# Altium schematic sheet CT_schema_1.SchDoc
size 526 x 490 mm
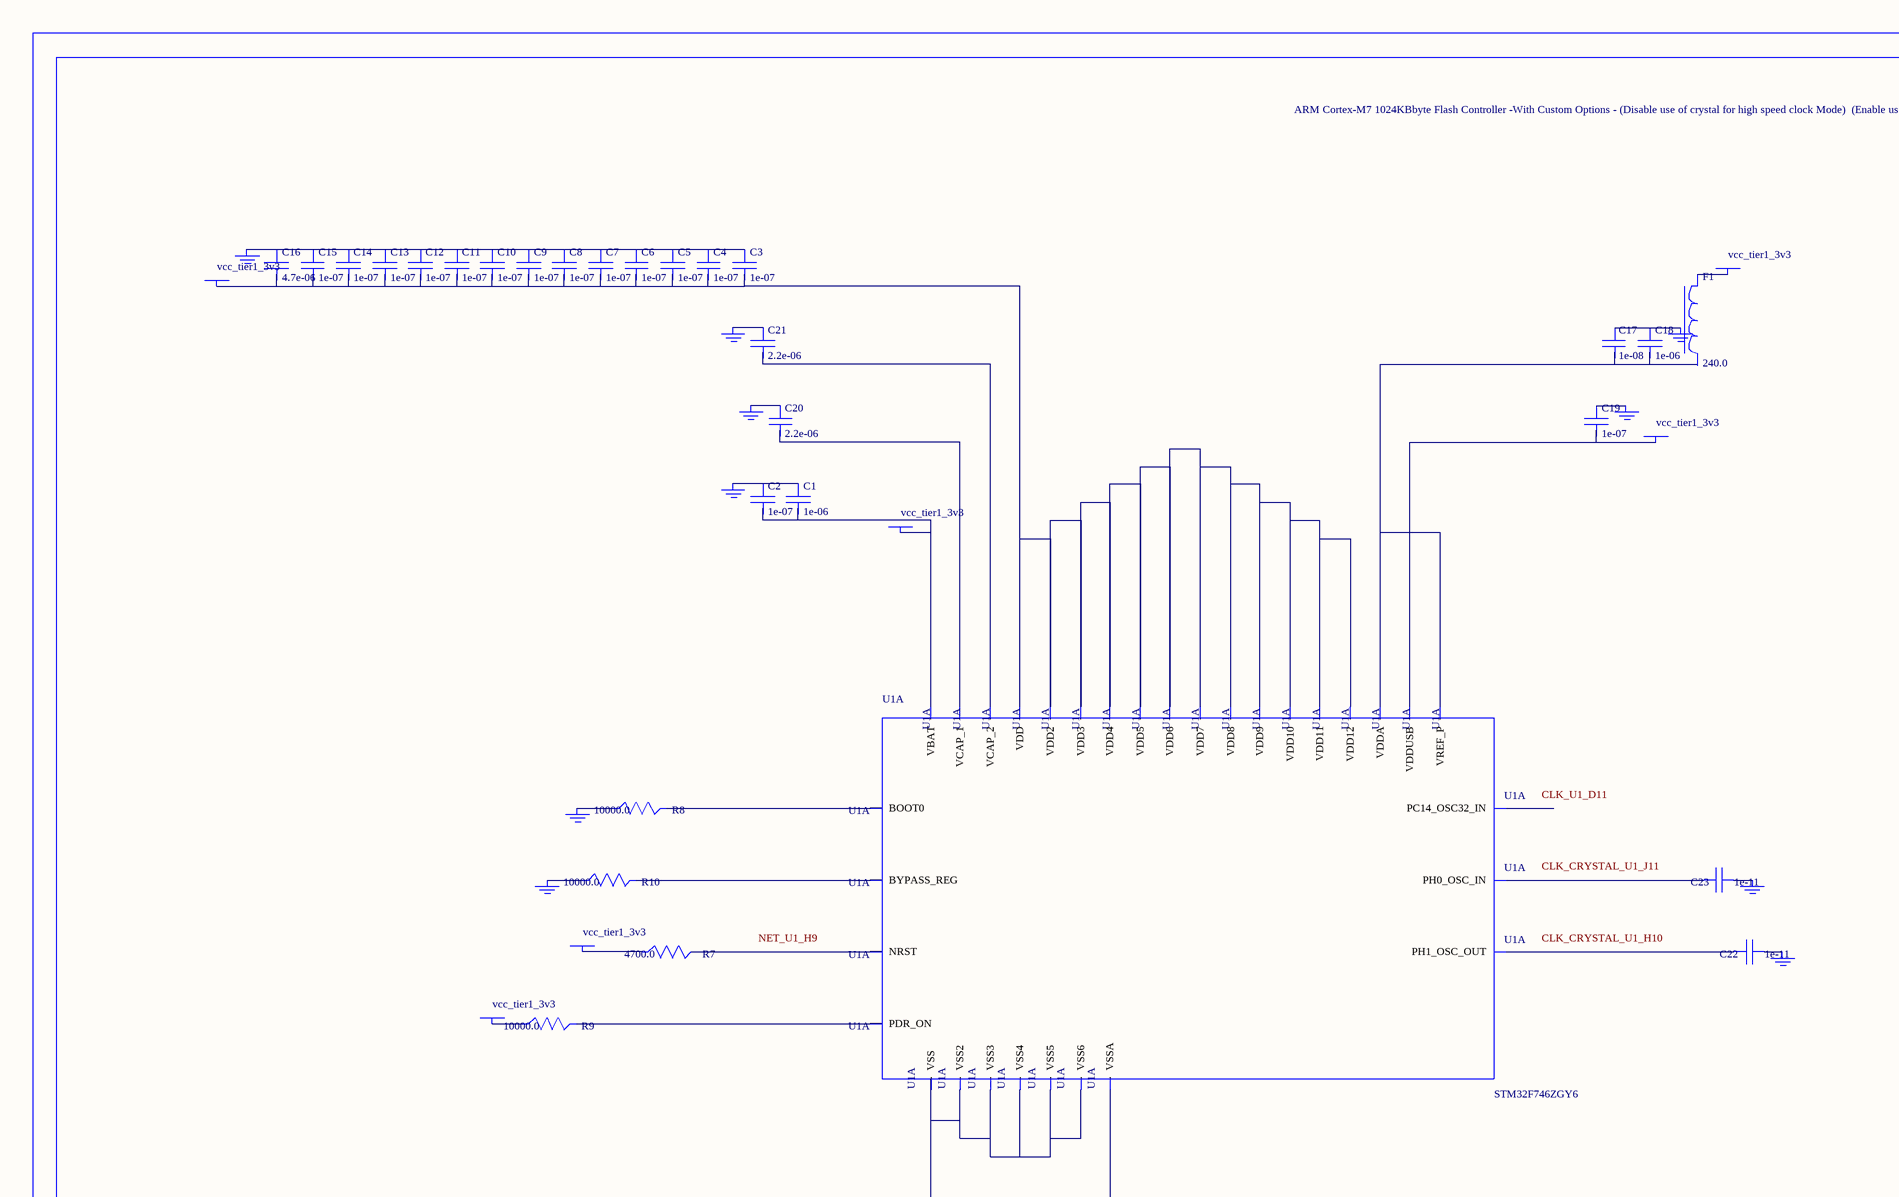
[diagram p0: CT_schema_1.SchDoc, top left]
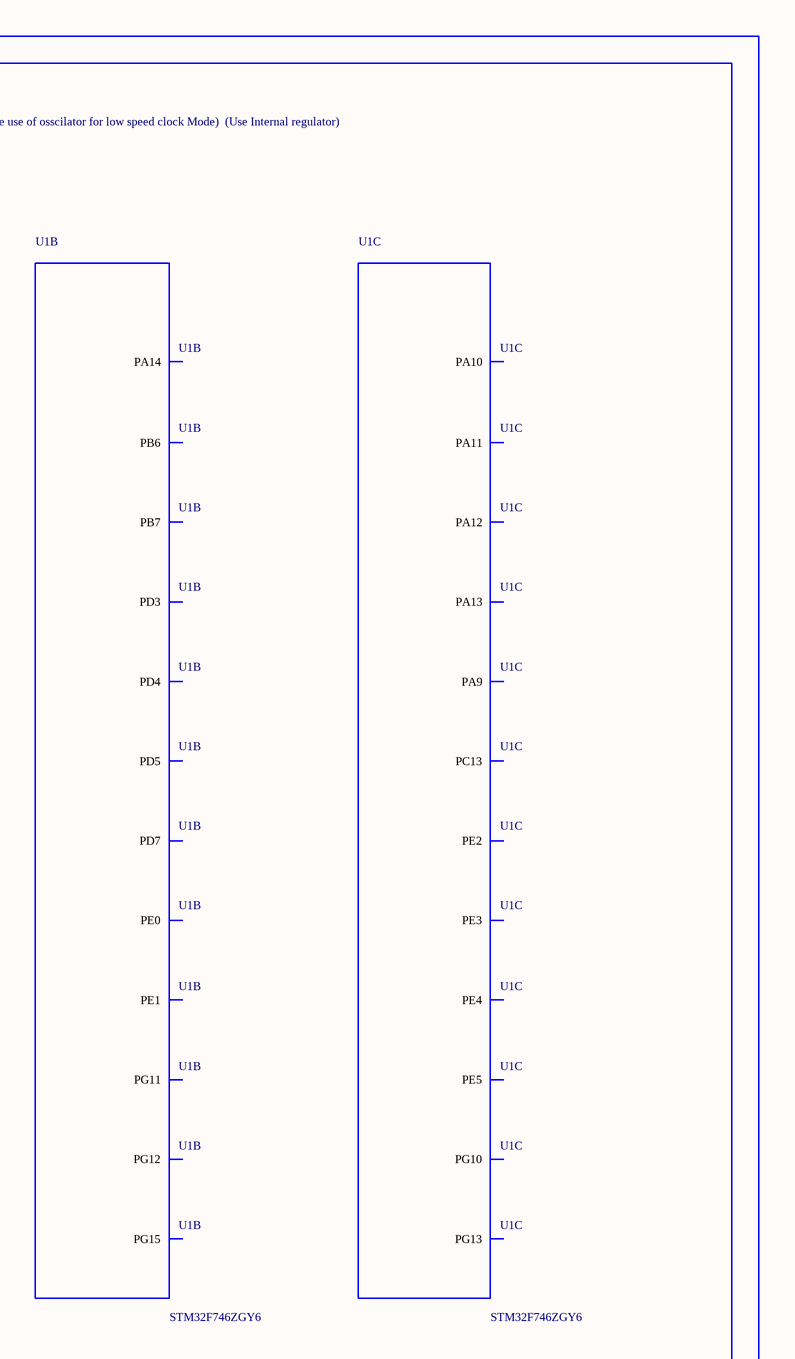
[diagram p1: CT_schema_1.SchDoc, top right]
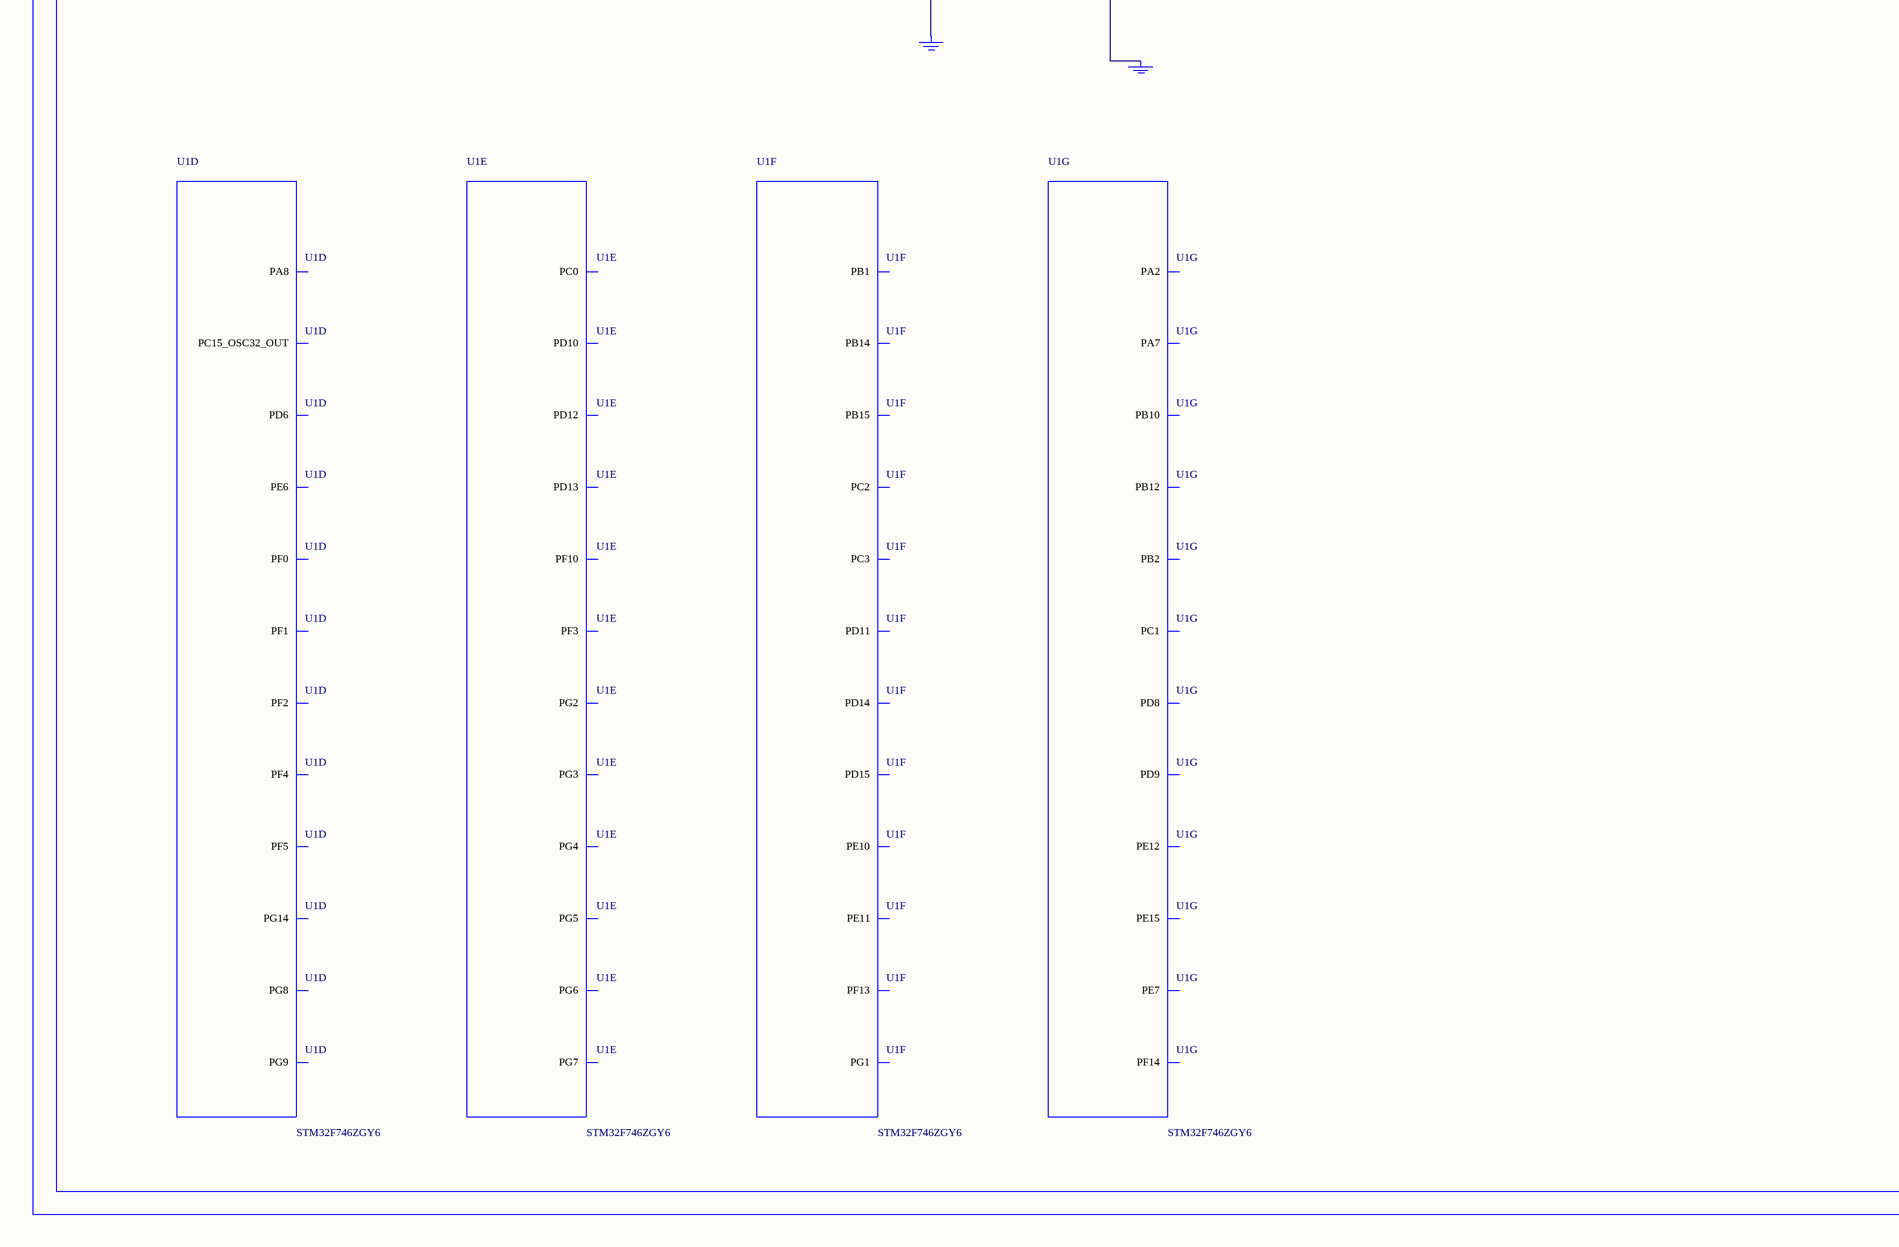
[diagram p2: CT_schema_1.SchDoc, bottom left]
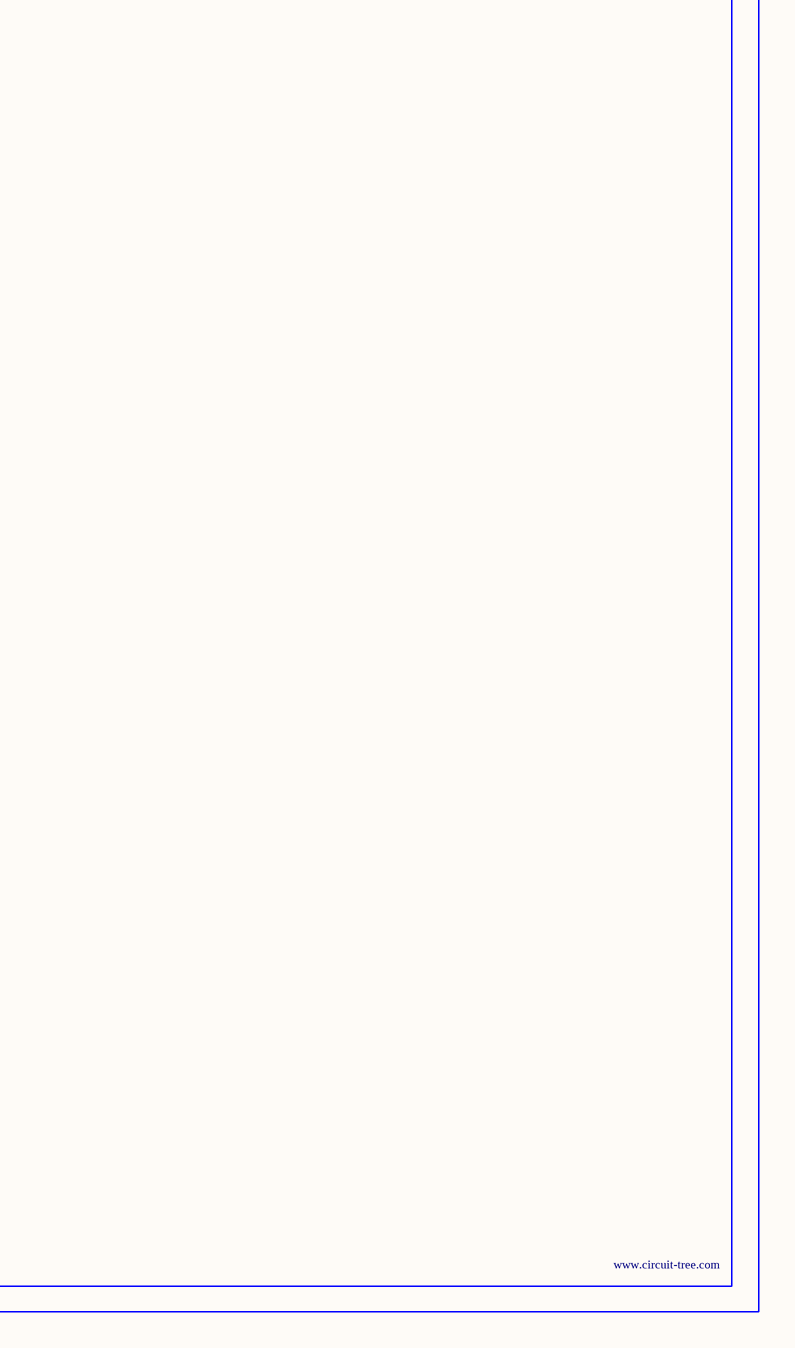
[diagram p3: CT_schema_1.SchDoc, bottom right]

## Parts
BORDER0  (no value)
C1  1e-06  [C0603]
C2  1e-07  [C0603]
C3  1e-07  [C0603]
C4  1e-07  [C0603]
C5  1e-07  [C0603]
C6  1e-07  [C0603]
C7  1e-07  [C0603]
C8  1e-07  [C0603]
C9  1e-07  [C0603]
C10  1e-07  [C0603]
C11  1e-07  [C0603]
C12  1e-07  [C0603]
C13  1e-07  [C0603]
C14  1e-07  [C0603]
C15  1e-07  [C0603]
C16  4.7e-06  [C0603]
C17  1e-08  [C0603]
C18  1e-06  [C0603]
C19  1e-07  [C0603]
C20  2.2e-06  [C0603]
C21  2.2e-06  [C0603]
C22  1e-11  [C0402]
C23  1e-11  [C0402]
F1  240.0  [L0603]
GND_INSTANCE_0_0  (no value)
GND_INSTANCE_0_1  (no value)
GND_INSTANCE_0_2  (no value)
GND_INSTANCE_0_3  (no value)
GND_INSTANCE_0_4  (no value)
GND_INSTANCE_0_5  (no value)
GND_INSTANCE_0_6  (no value)
GND_INSTANCE_0_7  (no value)
GND_INSTANCE_0_8  (no value)
GND_INSTANCE_0_9  (no value)
GND_INSTANCE_0_10  (no value)
GND_INSTANCE_0_11  (no value)
POWER_INSTANCE_0_0  vcc_tier1_3v3
POWER_INSTANCE_0_1  vcc_tier1_3v3
POWER_INSTANCE_0_2  vcc_tier1_3v3
POWER_INSTANCE_0_3  vcc_tier1_3v3
POWER_INSTANCE_0_4  vcc_tier1_3v3
POWER_INSTANCE_0_5  vcc_tier1_3v3
R7  4700.0  [R0603]
R8  10000.0  [R0603]
R9  10000.0  [R0603]
R10  10000.0  [R0603]
U1  STM32F746ZGY6  [WLCSP143]  (parts A,B,C,D,E,F,G of 13)

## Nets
NetC1_1: C1.1 C2.1 GND_INSTANCE_0_0.0(GND)
NetC1_2: C1.2 C2.2 POWER_INSTANCE_0_0.0(PWR) U1.C11(VBAT)
NetC3_1: C3.1 C4.1 C5.1 C6.1 C7.1 C8.1 C9.1 C10.1 C11.1 C12.1 C13.1 C14.1 C15.1 C16.1 GND_INSTANCE_0_2.0(GND)
NetC3_2: C3.2 C4.2 C5.2 C6.2 C7.2 C8.2 C9.2 C10.2 C11.2 C12.2 C13.2 C14.2 C15.2 C16.2 POWER_INSTANCE_0_2.0(PWR) U1.A1(VDD) U1.C1(VDD2) U1.C5(VDD3) U1.D7(VDD4) U1.E6(VDD6) U1.E10(VDD5) U1.G7(VDD7) U1.J5(VDD8) U1.J6(VDD9) U1.J7(VDD10) U1.J8(VDD11) U1.L1(VDD12)
NetC17_1: C17.1 C18.1 GND_INSTANCE_0_1.0(GND)
NetC17_2: C17.2 C18.2 U1.L10(VDDA) U1.L11(VREF_P)
NetC19_1: C19.1 GND_INSTANCE_0_4.0(GND)
NetC19_2: C19.2 POWER_INSTANCE_0_4.0(PWR) U1.G1(VDDUSB)
NetC20_1: C20.1 GND_INSTANCE_0_6.0(GND)
NetC20_2: C20.2 U1.N2(VCAP_1)
NetC21_1: C21.1 GND_INSTANCE_0_7.0(GND)
NetC21_2: C21.2 U1.D1(VCAP_2)
NetC22_1: C22.1 GND_INSTANCE_0_8.0(GND)
NetC22_2: C22.2 U1.H10(PH1_OSC_OUT)
NetC23_1: C23.1 GND_INSTANCE_0_9.0(GND)
NetC23_2: C23.2 U1.J11(PH0_OSC_IN)
NetF1_1: F1.1 POWER_INSTANCE_0_1.0(PWR)
NetGND_INSTANCE_0_3_0: GND_INSTANCE_0_3.0(GND) R8.1
NetGND_INSTANCE_0_5_0: GND_INSTANCE_0_5.0(GND) R10.1
NetGND_INSTANCE_0_10_0: GND_INSTANCE_0_10.0(GND) U1.K10(VSSA)
NetGND_INSTANCE_0_11_0: GND_INSTANCE_0_11.0(GND) U1.D2(VSS) U1.E7(VSS2) U1.F5(VSS3) U1.H2(VSS4) U1.H3(VSS5) U1.H7(VSS6)
NetPOWER_INSTANCE_0_3_0: POWER_INSTANCE_0_3.0(PWR) R9.1
NetPOWER_INSTANCE_0_5_0: POWER_INSTANCE_0_5.0(PWR) R7.1
NetR7_2: R7.2 U1.H9(NRST)
NetR8_2: R8.2 U1.C9(BOOT0)
NetR9_2: R9.2 U1.A11(PDR_ON)
NetR10_2: R10.2 U1.N11(BYPASS_REG)

Not connected (* = marked no-connect by the designer): F1 2; U1 A4(PD5) A5(PD7) A6(PG12) A7(PG15) A8(PB6) A10(PE1) B1(PA14) B4(PD3) B5(PD4) B6(PG11) B8(PB7) B10(PE0) B11(PE4) C6(PG10) C10(PE3) D3(PA13) D4(PA11) D5(PA10) D6(PG13) D8(PE2) D9(PE5) D10(PC13) D11(PC14_OSC32_IN) E1(PA12) E2(PA9) E5(PG9) E8(PE6) E9(PF1) E11(PC15_OSC32_OUT) F1(PA8) F4(PD6) F6(PG14) F8(PF5) F9(PF4) F10(PF2) F11(PF0) G2(PG8) G3(PG3) G4(PG6) G5(PG4) G6(PG5) G9(PF10) G11(PF3) H1(PG7) H4(PD10) H5(PD13) H6(PD12) H8(PC0) J1(PG2) J2(PD14) J3(PB15) J4(PE10) J9(PC3) J10(PC2) K1(PD15) K2(PD11) K3(PB14) K4(PE11) K5(PG1) K6(PF13) K7(PB1) K11(PC1) L2(PD8) L3(PE15) L4(PE12) L5(PE7) L6(PF14) L7(PB2) L8(PA7) L9(PA2) M1(PD9) M2(PB12) M3(PB10)

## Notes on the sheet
- Labels drawn without touching a wire or pin: CLK_CRYSTAL_U1_H10, CLK_CRYSTAL_U1_J11, CLK_U1_D11, NET_U1_H9

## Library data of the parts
BORDER0 = BORDER_PAGE0
C1 C18 = C0603C105K3RACTU
C2-C15 C19 = 06035C104K4Z2A
C16 = GRM188R6YA475KE15D
C17 = 06035C103K4Z2A
C20 C21 = C0603C225K8RACTU
C22 C23 = C0402C100K3GACTU
F1 = Z0603C241ASMST
GND_INSTANCE_0_0-GND_INSTANCE_0_11 = GND
POWER_INSTANCE_0_0-POWER_INSTANCE_0_5 = PWR
R7 = RC0603JR-074K7L
R8-R10 = RC0603JR-0710KL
